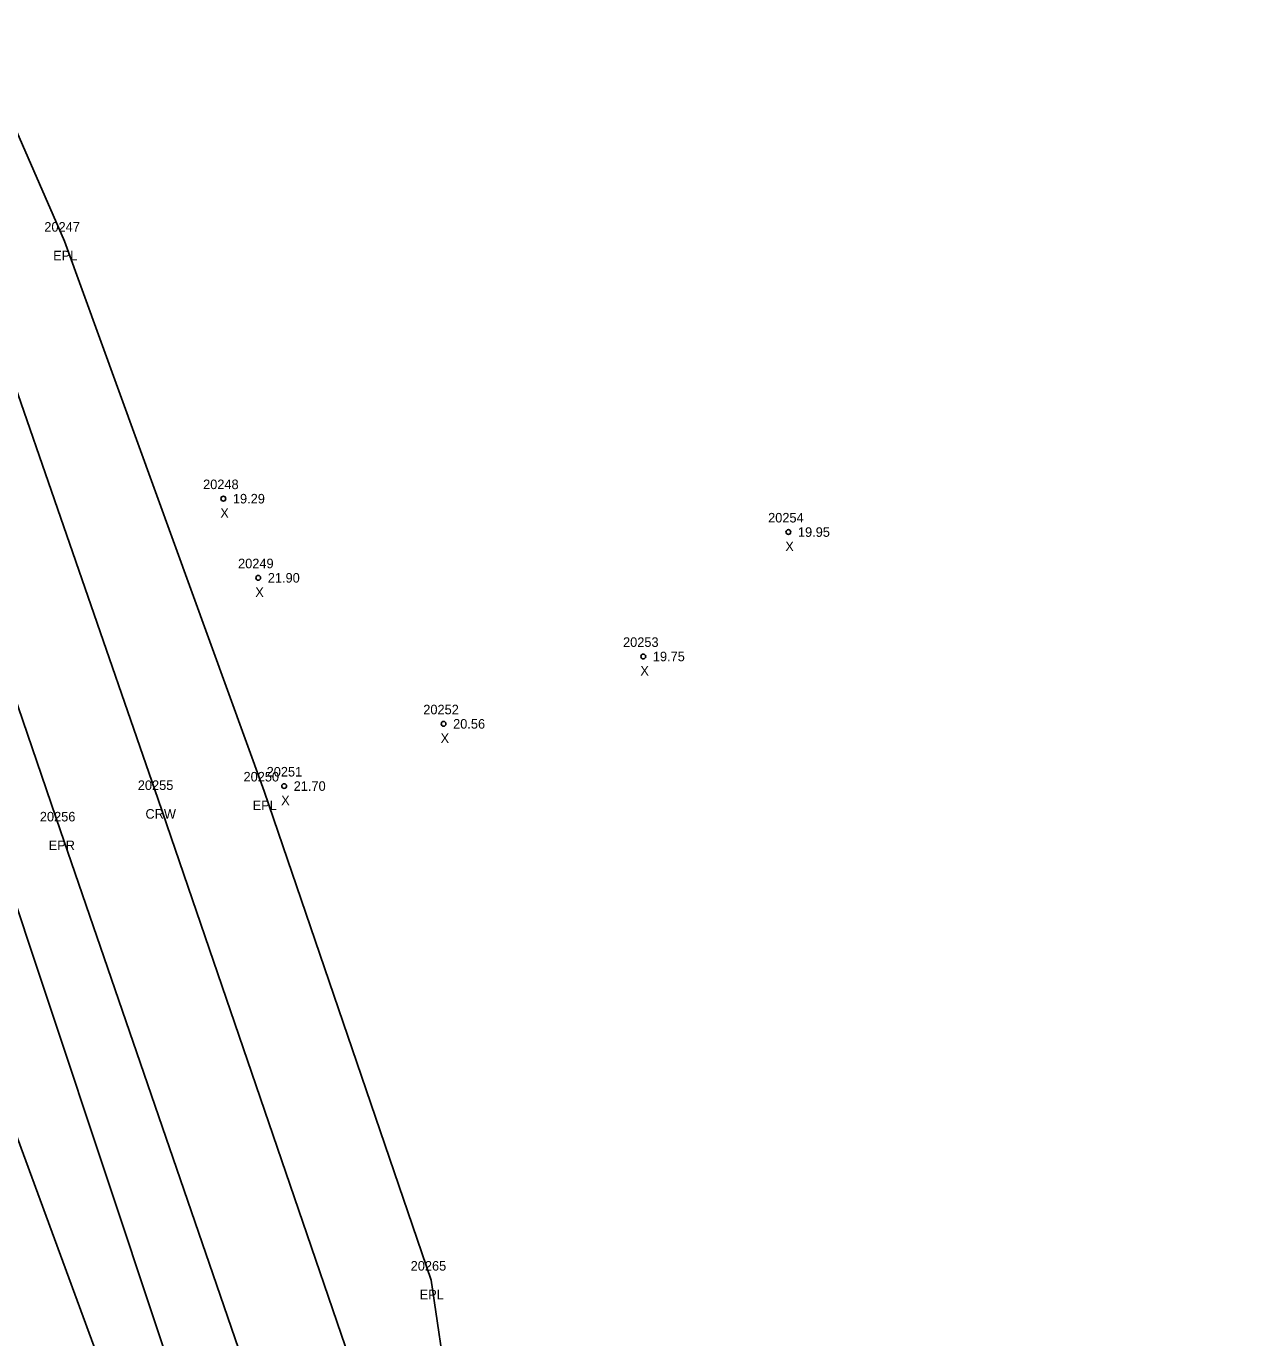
# Model space of a CAD drawing. Extents: x 2432729 to 2433340, y 684958 to 688103.
# Drawn here: x 2433027.9 to 2433155.8, y 686613.4 to 686750.6 of the extents above; entities that cross this region are included whole.
import ezdxf

# ---------------------------------------------------------------- set-up
doc = ezdxf.new("R2010")
doc.units = 0
for name, color, linetype in [('RD_DTM_BkLn1', 7, 'Continuous'), ('RD_DTM_BkLn2', 7, 'Continuous'), ('RD_EX_Road', 7, 'Continuous'), ('RD_EX_Road_txCode', 7, 'Continuous'), ('RD_Sketch8', 7, 'Continuous'), ('RD_SMD_Locator', 7, 'Continuous'), ('RD_SMD_Misc', 7, 'Continuous')]:
    doc.layers.add(name, color=color, linetype=linetype)

msp = doc.modelspace()

# ---------------------------------------------------------------- linework, layer by layer
at = {"layer": 'RD_DTM_BkLn1'}
for points in [[(2432926.02, 687213.66), (2432924.35, 687158.94), (2432925.68, 687108.84), (2432939.7, 687000.92), (2432956.93, 686927.39), (2432975, 686866.8), (2433007.19, 686769.33), (2433041.66, 686669.67), (2433075.97, 686569.51), (2433108.49, 686474.01), (2433123.82, 686426.48), (2433137.99, 686374.7), (2433148.76, 686320.1), (2433154.8, 686269.16), (2433155.78, 686212.93), (2433152.37, 686164.52), (2433145.67, 686113.9), (2433140.38, 686078.83)], [(2432898.98, 687049.37), (2432906.9, 687044.55), (2432919.33, 686997.25), (2432938.84, 686920.72), (2432957.15, 686862.46), (2432990.45, 686763.71), (2433024.84, 686664.51), (2433058.68, 686562.8), (2433090.41, 686467.11), (2433107.21, 686420.87), (2433120.26, 686369.86), (2433132.05, 686313.5), (2433136.59, 686267.4), (2433133.92, 686213.17), (2433133.74, 686165.58), (2433125.69, 686115.89), (2433123.08, 686088.41), (2433128.09, 686081.14)]]:
    msp.add_lwpolyline(points, dxfattribs=at)
at = {"layer": 'RD_DTM_BkLn2'}
msp.add_lwpolyline([(2432916.74, 686973.9), (2432925.37, 686926.35), (2432950.18, 686859.06), (2432982.46, 686761.59), (2433017.67, 686659.38), (2433053.8, 686561.16), (2433080.54, 686460.75), (2433098.39, 686424.64), (2433113.62, 686368.79), (2433123.31, 686312.63), (2433128.29, 686266.56), (2433126.49, 686214.47), (2433123.88, 686164.31), (2433114.46, 686111.82), (2433110.48, 686084.68), (2433120.95, 686072.12)], dxfattribs=at)
at = {"layer": 'RD_EX_Road'}
for points in [[(2432915.64, 687215.4), (2432913.86, 687159.12), (2432915.08, 687107.55), (2432919.97, 687053.4), (2432928.7, 686998.89), (2432946.77, 686924.59), (2432964.57, 686864), (2432997.3, 686766.34), (2433031.44, 686666.38), (2433066.06, 686565.78), (2433098.73, 686469.74), (2433113.88, 686422.91), (2433127.93, 686372.14), (2433139.1, 686314.76), (2433144.47, 686268.02), (2433145.44, 686213), (2433142.32, 686164.92), (2433135.44, 686115.75), (2433128.09, 686081.14)], [(2432937.12, 687213.43), (2432935.51, 687158.7), (2432936.54, 687110.38), (2432944.97, 687033.04), (2432950.24, 687002.26), (2432966.49, 686930.23), (2432984.9, 686870.1), (2433011.7, 686787.41), (2433010.33, 686784.51), (2433011.78, 686772.99), (2433015.37, 686760.79), (2433021.02, 686752.9), (2433031.88, 686728.09), (2433052.76, 686670.56), (2433070.23, 686619.38), (2433072.02, 686607.31)]]:
    msp.add_lwpolyline(points, dxfattribs=at)
at = {"layer": 'RD_SMD_Locator'}
for centre, radius in [((2433031.88, 686728.09), 0.001), ((2433048.49, 686701.15), 0.25), ((2433107.61, 686697.66), 0.25), ((2433052.14, 686692.87), 0.25), ((2433092.43, 686684.64), 0.25), ((2433071.53, 686677.59), 0.25), ((2433052.76, 686670.56), 0.001), ((2433054.85, 686671.08), 0.25), ((2433041.66, 686669.67), 0.001), ((2433031.44, 686666.38), 0.001), ((2433070.23, 686619.38), 0.001)]:
    msp.add_circle(centre, radius, dxfattribs=at)

# ---------------------------------------------------------------- texts
at = {"layer": 'RD_EX_Road_txCode'}
for s, p in [('20247', (2433029.76, 686729.09)), ('EPL', (2433030.68, 686726.09)), ('20250', (2433050.6, 686671.56)), ('EPL', (2433051.55, 686668.56)), ('20256', (2433029.29, 686667.38)), ('EPR', (2433030.21, 686664.38)), ('20265', (2433068.09, 686620.38)), ('EPL', (2433069.03, 686617.38))]:
    msp.add_text(s, height=1, dxfattribs=at).set_placement(p)
at = {"layer": 'RD_Sketch8'}
for s, p in [('20248', (2433046.37, 686702.15)), ('19.29', (2433049.49, 686700.65)), ('X', (2433048.17, 686699.15)), ('20254', (2433105.49, 686698.66)), ('19.95', (2433108.61, 686697.16)), ('X', (2433107.29, 686695.66)), ('20249', (2433050.03, 686693.87)), ('21.90', (2433053.14, 686692.37)), ('X', (2433051.83, 686690.87)), ('20253', (2433090.31, 686685.64)), ('19.75', (2433093.43, 686684.14)), ('X', (2433092.12, 686682.64)), ('20252', (2433069.41, 686678.59)), ('20.56', (2433072.53, 686677.09)), ('X', (2433071.22, 686675.59)), ('20251', (2433053.02, 686672.08)), ('21.70', (2433055.85, 686670.58)), ('X', (2433054.54, 686669.08))]:
    msp.add_text(s, height=1, dxfattribs=at).set_placement(p)
at = {"layer": 'RD_SMD_Misc'}
for s, p in [('20255', (2433039.54, 686670.67)), ('CRW', (2433040.34, 686667.67))]:
    msp.add_text(s, height=1, dxfattribs=at).set_placement(p)

doc.saveas('drawing.dxf')
